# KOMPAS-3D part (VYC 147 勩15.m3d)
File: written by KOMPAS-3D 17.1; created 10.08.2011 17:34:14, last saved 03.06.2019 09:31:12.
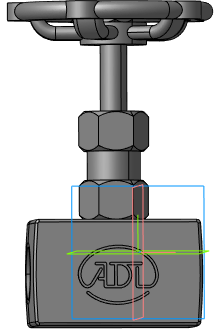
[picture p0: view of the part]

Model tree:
1. Плоскость XY
2. Плоскость ZX
3. Плоскость ZY
4. Ось X
5. Ось Y
6. Ось Z
7. Начало координат
8. Операция без истории:2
